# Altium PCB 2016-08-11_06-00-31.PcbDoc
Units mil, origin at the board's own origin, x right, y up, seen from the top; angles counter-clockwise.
Board outline 3200 x 1980 mil, 4 copper layers (Top Layer, MidLayer1, MidLayer2, Bottom Layer); 36 components, 23 nets, 100 pads, 94 vias.
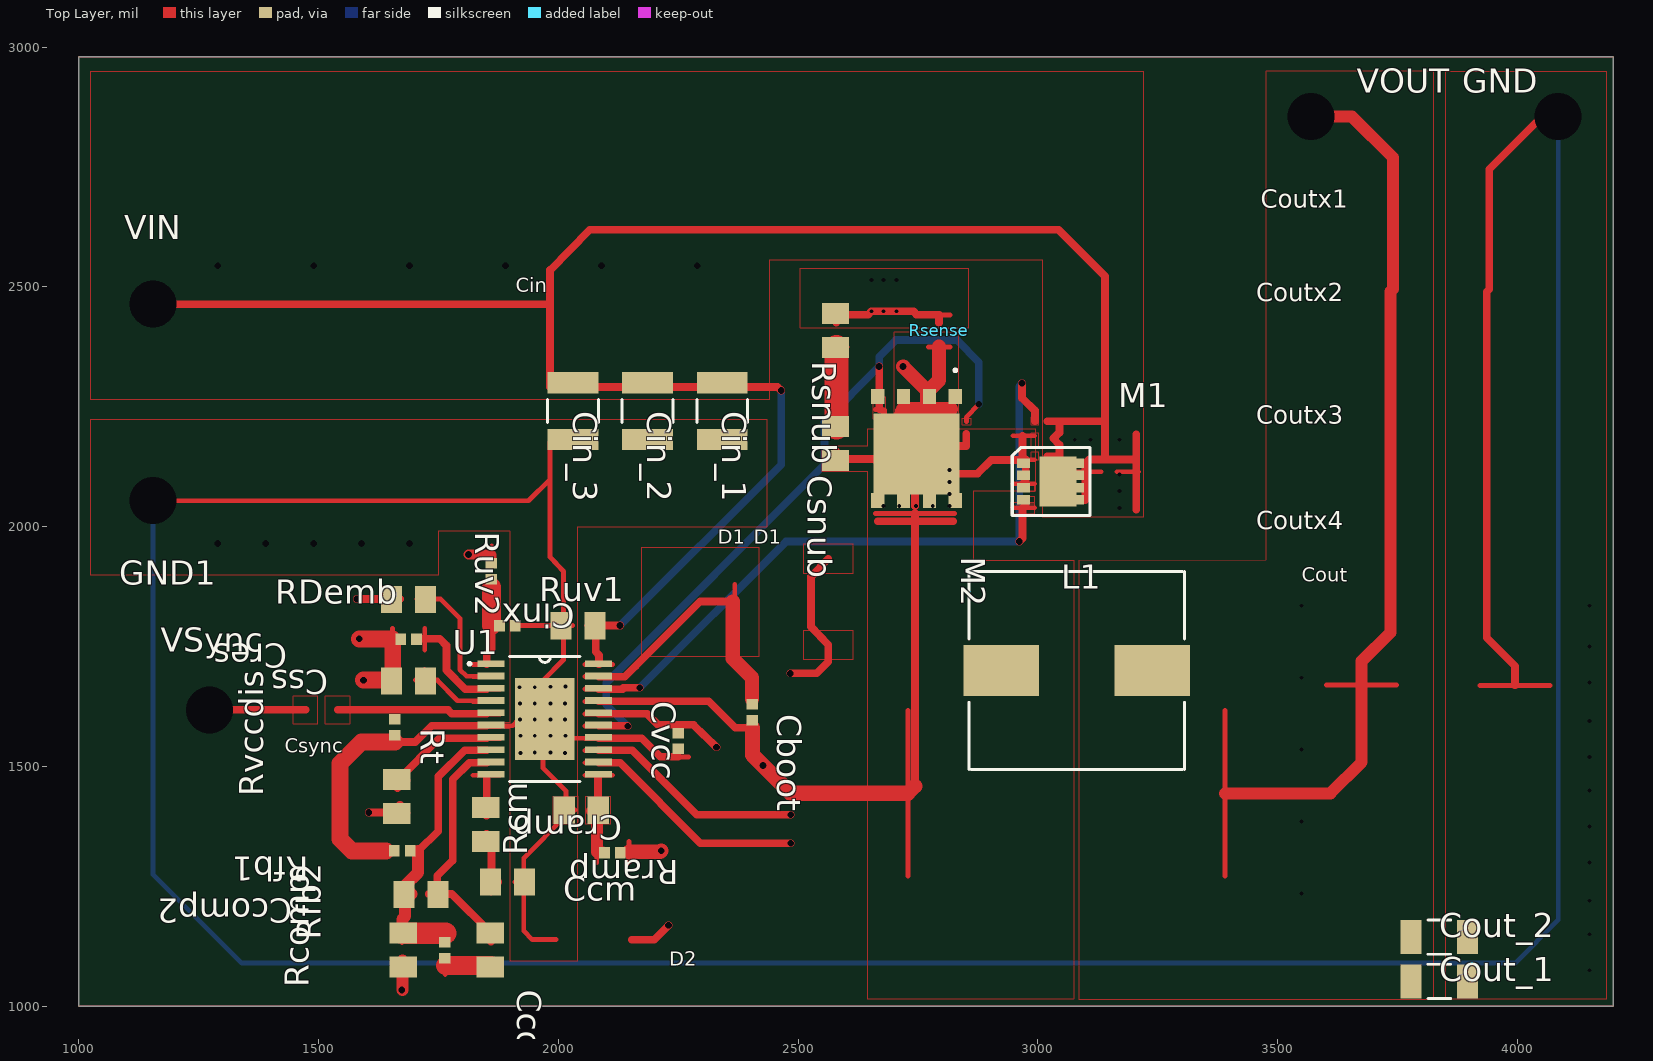
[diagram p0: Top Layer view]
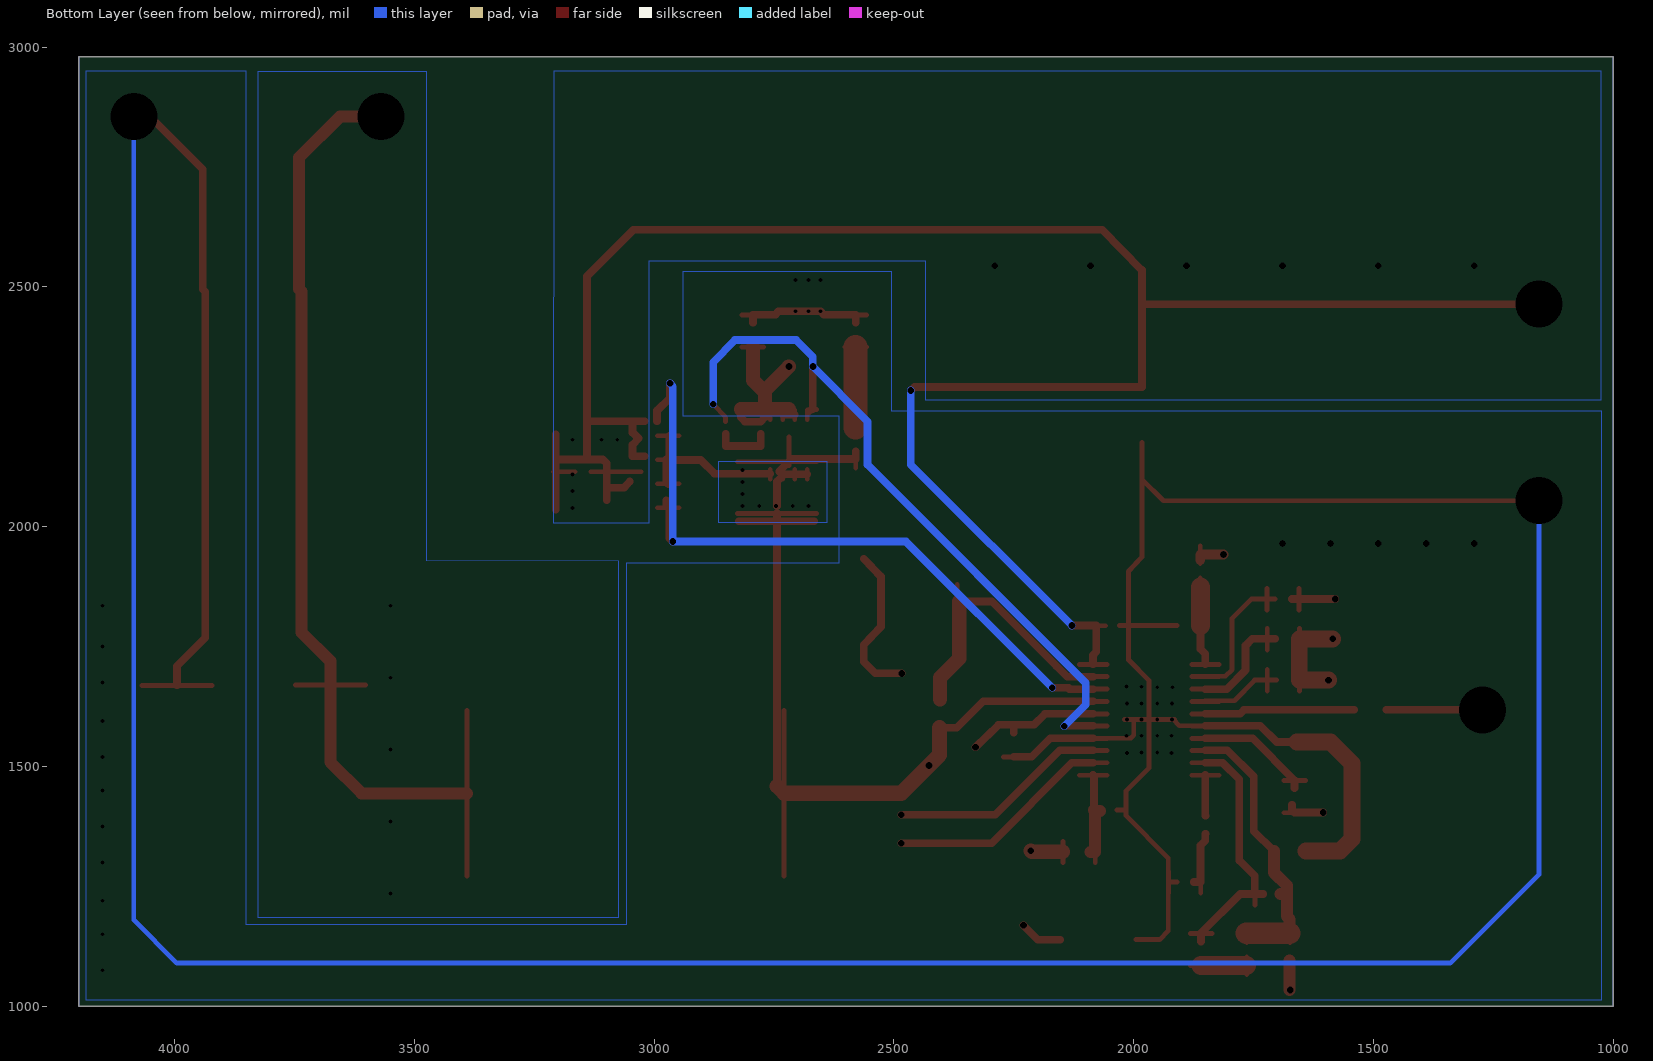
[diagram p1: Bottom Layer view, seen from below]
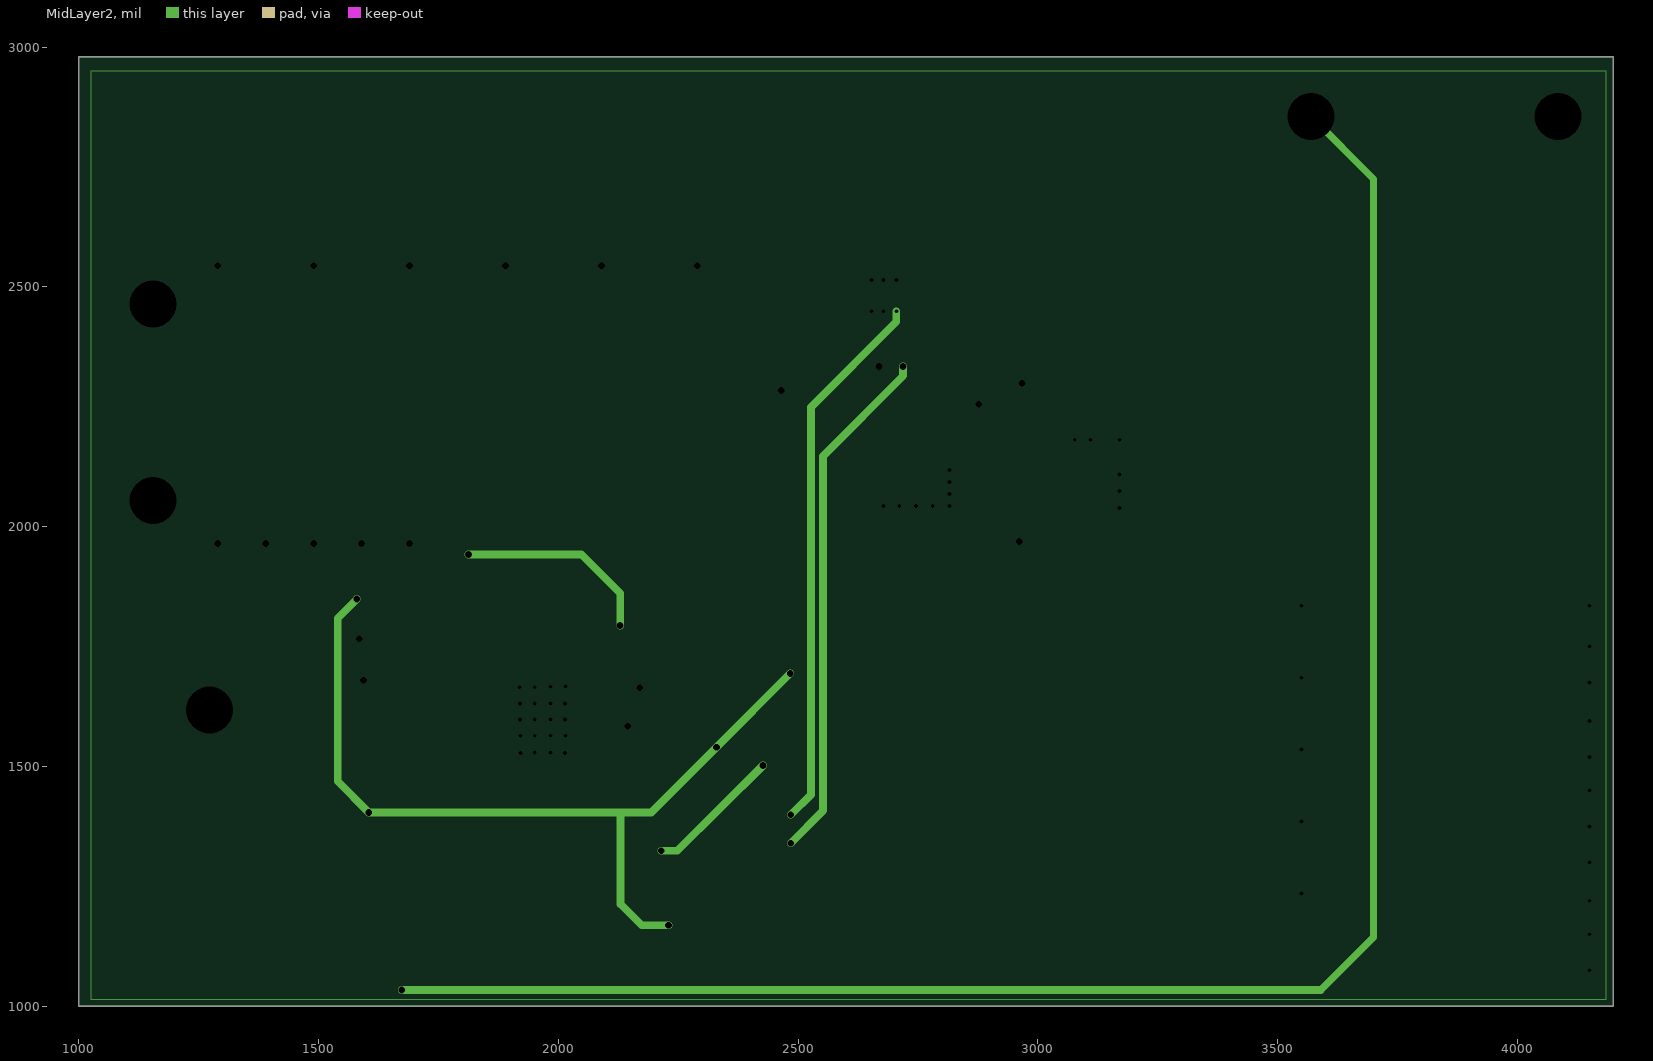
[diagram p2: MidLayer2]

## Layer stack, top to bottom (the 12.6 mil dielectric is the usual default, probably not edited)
Top Layer: signal copper 1.4
Dielectric: core 12.6, FR-4, Dk 4.8
MidLayer1: signal copper 1.4
Dielectric: prepreg 12.6, FR-4, Dk 4.8
MidLayer2: signal copper 1.4
Dielectric: core 12.6, FR-4, Dk 4.8
Bottom Layer: signal copper 1.4

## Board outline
1000,1000 4200,1000 4200,2980 1000,2980

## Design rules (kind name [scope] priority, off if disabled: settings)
PlaneConnect [All] p0: scope1count=1 scope1_0_kind=Board scope1_0_value=Board scope2count=1 scope2_0_kind=Board scope2_0_value=Board commentlength=0 planeconnectstyle=Direct reliefexpansion=20 reliefentries=4 reliefconductorwidth=10 reliefairgap=10
PlaneConnect [All] p1: planeconnectstyle=Direct reliefexpansion=20 reliefentries=4 reliefconductorwidth=10 reliefairgap=10
PolygonConnect [All] p0: scope1count=1 scope1_0_kind=Board scope1_0_value=Board scope2count=1 scope2_0_kind=Board scope2_0_value=Board commentlength=0 connectstyle=Direct reliefconductorwidth=10 reliefentries=4 polygonreliefangle="90 Angle"
PolygonConnect [All] p1: connectstyle=Direct reliefconductorwidth=10 reliefentries=4 polygonreliefangle="90 Angle"

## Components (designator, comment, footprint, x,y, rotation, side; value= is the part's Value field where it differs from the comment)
Cboot "" 0402#1 2405,1613 r270 top
Ccm "" 0805 1894,1259 r0 top
Ccomp1 "" 0805 1858,1117 r270 top
Ccomp2 "" 0805 1714,1233 r180 top
Cin_1 "" 1210_280 2342,2241 r270 top
Cin_2 "" 1210_280 2186,2241 r270 top
Cin_3 "" 1210_280 2031,2241 r270 top
Cinx "" 0805 2041,1793 r180 top
Cout_1 "" 1206_190 3837,1052 r0 top
Cout_2 "" 1206_190 3837,1144 r0 top
Cramp "" 0805 2048,1409 r180 top
Cres "" 0402#1 1688,1765 r180 top
Csnub "" 0805 2578,2173 r270 top
Css "" 0805 1688,1678 r180 top
Cvcc "" 0402#1 2250,1553 r270 top
GND "" TP-1502 4084,2853 r0 top
GND1 "" TP-1502 1155,2052 r0 top
L1 "" MLC1260 3081,1700 r0 top
M1 "" TRANS_NexFET_Q3 3034,2094 r0 top
M2 "" TRANS_NexFET_Q5A 2747,2163 r270 top
Rcm "" 0805 1849,1379 r90 top
Rcomp "" 0402#1 1763,1117 r90 top
RDemb "" 0805 1688,1848 r0 top
Rfb1 "" 0402#1 1675,1324 r180 top
Rfb2 "" 0805 1677,1117 r90 top
Rramp "" 0402#2 2113,1320 r180 top
Rsense "" 0612 2793,2409 r90 top
Rsnub "" 0805 2578,2409 r270 top
Rt "" 0402#1 1659,1582 r270 top
Ruv1 "" 0402#1 1894,1793 r0 top
Ruv2 "" 0402#1 1860,1907 r270 top
Rvccdis "" 0805 1663,1437 r90 top
U1 "" PWP0020A 1972,1599 r0 top
VIN "" TP-1502 1155,2462 r0 top
VOUT "" TP-1502 3568,2853 r0 top
VSync "" TP-1502 1275,1619 r0 top

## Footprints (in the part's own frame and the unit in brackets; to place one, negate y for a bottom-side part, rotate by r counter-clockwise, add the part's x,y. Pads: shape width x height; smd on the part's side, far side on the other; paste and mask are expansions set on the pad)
0402#1 [mil]
  rect 22x24 smd: 1(-16.5,0) 2(16.5,0)
0402#2 [mil]
  rect 22x24 smd: 1(-16.5,0) 1(-16.5,0) 2(16.5,0) 2(16.5,0)
0612 [mil]
0805 [mil]
  rect 44x57 smd: 1(-35.5,0) 2(35.5,0)
1206_190 [mil]
  rect 44x71 smd: 1(-59,0) 2(59,0)
  silkscreen extent -24,-36 24,36
1210_280 [mil]
  rect 44x106 smd: 1(-59,0) 2(59,0)
  silkscreen extent -24,-53 24,53
MLC1260 [mil]
  rect 157.5x106 smd: 1(-157.25,0) 2(157.25,0)
  silkscreen extent -224,-206 224,206
PWP0020A [mil]
  rect 56x14 smd: 1(-112,115.16) 2(-112,89.57) 3(-112,63.98) 4(-112,38.39) 5(-112,12.8) 6(-112,-12.8) 7(-112,-38.39) 8(-112,-63.98) 9(-112,-89.57) 10(-112,-115.16) 11(112,-115.16) 12(112,-89.57) 13(112,-63.98) 14(112,-38.39) 15(112,-12.8) 16(112,12.8) 17(112,38.39) 18(112,63.98) 19(112,89.57) 20(112,115.16)
  rect 124x171 smd: 21(0,0)
  silkscreen extent -160,-130 74,130
TP-1502 [mil]
  round 65 / inner round 0 / far side round 65 hole 32: 1(0,0)
TRANS_NexFET_Q3 [mm]
  rect 0.68x0.5 smd: 1(-1.625,0.975) 2(-1.625,0.325) 3(-1.625,-0.325) 4(-1.625,-0.975)
  rect 0.41x0.5 smd: 5(1.385,-0.975) 6(1.385,-0.325) 7(1.385,0.325) 8(1.385,0.975)
  rect 1.96x2.65 smd: 9(0.205,0)
  silkscreen extent -2.21,-1.8 1.9,1.8
TRANS_NexFET_Q5A [mm]
  rect 0.8x0.7 smd: 1(-2.752,2.055) 2(-2.752,0.685) 3(-2.752,-0.685) 4(-2.752,-2.055) 5(2.752,-2.055) 6(2.752,-0.685) 7(2.752,0.685) 8(2.752,2.055)
  rect 4.3x4.56 smd: 9(0.3,0)
  silkscreen extent -4.22,1.98 -4.07,2.13

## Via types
v1: diameter 0, hole 8, Top Layer to Bottom Layer, 56 vias
v2: diameter 0, hole 14, Top Layer to Bottom Layer, 33 vias
v3: diameter 0, hole 98, Top Layer to Bottom Layer, 5 vias

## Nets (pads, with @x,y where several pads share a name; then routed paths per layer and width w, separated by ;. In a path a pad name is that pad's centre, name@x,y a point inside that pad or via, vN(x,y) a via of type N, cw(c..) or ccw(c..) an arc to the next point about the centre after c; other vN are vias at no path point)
0: Ccm.2 Cin_1.2 Cin_2.2 Cin_3.2 Cinx.2 Cout_1.2 Cout_2.2 Cramp.2 Cres.2 Css.2 Cvcc.2 GND1.1 GND.1 Rfb1.2 Rsnub.1 Rt.2 Ruv1.2 U1.6 U1.13 U1.14 U1.21 | length 12873.8
  Top Layer w10: v3(1155,2054) 1938,2054 1983,2099 ; 1637,1550.5 1682,1550.5 ; Css.2@1654.5,1657 Css.2@1654.5,1702 ; 1654.5,1743 1654.5,1788 ; 1822,1584.5 U1.6@1879,1584.5 ; U1.6@1851,1585 1905,1585 1918,1598 U1.21@1968,1598 ; Ccm.2@1910,1259 Ccm.2@1928,1259 ; Ruv1.2@1910,1794 Cinx.2@2011,1794 ; U1.21@1915,1598 U1.21@2020,1598 ; Ccm.2@1927.5,1236 Ccm.2@1927.5,1281 ; Cin_3.2@1983,2176 1983,2099 ; Cinx.2@1992,1793.5 2029,1793.5 ; 1996,1139 1946,1139 1928,1157 Ccm.2@1928,1259 ; 2030,1794 Cinx.2@2011,1794 ; 2035,1409 Cramp.2@2016,1409 ; U1.13@2056,1533.5 2113,1533.5 ; U1.14@2056,1558.5 2113,1558.5 ; U1.14@2085,1559 2006,1559 2000,1565 2000,1598 U1.21@1968,1598 ; 2227,1519.5 2272,1519.5 ; Rsnub.1@2557,2441.5 Rsnub.1@2602,2441.5 ; 2772,2441.5 2817,2441.5 ; 3922,1669 4068,1669 ; Ccm.2@1928,1259 1928,1309 2016,1397 Cramp.2@2016,1409 ; U1.21@1968,1598 1968,1497 2016,1449 Cramp.2@2016,1409 ; U1.21@1968,1598 1968,1679 2011,1722 Cinx.2@2011,1794 ; 1983,2099 1983,1936 2011,1907 Cinx.2@2011,1794
  Top Layer w16: 1660,1551 1702,1551 1736,1585 U1.6@1851,1585 ; U1.13@2085,1534 2154,1534 2289,1399 v2(2485,1399) ; U1.14@2085,1559 2174,1559 2213,1520 2250,1520 ; Rsnub.1@2580,2425 2580,2442 2646,2442 v1(2653,2449) v1(2678,2449) v1(2705,2449) 2741,2449 2747,2442 2794,2442 2794,2425 ; 3995,1669 3995,1709 3936,1768 3936,2000 3936,2245 3936,2490 3941,2495 3941,2745 4051,2855 v3(4085,2855)
  Top Layer w35: v2(1585,1766) 1655,1766 1655,1680 v2(1594,1680) ; 1641,1324 1570,1324 1545,1349 1545,1506 1590,1551 1660,1551
  MidLayer2 w16: v2(2485,1399) 2527,1441 2527,2249 2705,2427 v1(2705,2449)
  Bottom Layer w10: v3(1155,2054) 1155,1275 1340,1090 3995,1090 4085,1180 v3(4085,2855)
  other v1: 4150,1075 4150,1150 4150,1220 4150,1300 4150,1375 4150,1450 4150,1520 1921,1528 2014,1528 1951,1529 1984,1529 1921,1564 1951,1564 1984,1564 2015,1564 4150,1595 1920,1598 1951,1598 1984,1598 2014,1598 1920,1631 1951,1631 1984,1631 2014,1631 1919,1665 1951,1665 1984,1666 2015,1667 4150,1675 4150,1750 4150,1835 2653,2514 2678,2514 2705,2514
  other v2: 1290,1965 1390,1965 1490,1965 1590,1965 1690,1965
1: Cin_1.1 Cin_2.1 Cin_3.1 Cinx.1 M1.5 M1.6 M1.7 M1.8 M1.9 Ruv2.1 U1.20 VIN.1 | length 5318.6
  Top Layer w10: Ruv2.1@1861.5,1923 1861.5,1960 ; U1.20@2056,1712.5 2113,1712.5 ; Cinx.1@2059,1793.5 Cinx.1@2096,1793.5 ; M1.9@3027,2114.5 3132,2114.5 ; 3165,2114.5 3210,2114.5
  Top Layer w16: v3(1155,2464) 1983,2464 ; U1.20@2085,1713 2085,1732 2078,1739 2078,1794 v2(2129,1794) ; v2(2465,2284) 2457,2291 1983,2291 1983,2464 ; 3020,2147 3045,2147 3045,2171 3032,2184 3045,2196 3045,2220 ; 3020,2220 3045,2220 ; M1.9@3051,2094 3063,2081 3099,2081 ; 3099,2055 3099,2081 ; 3140,2140 3140,2224 ; 3205,2035 3205,2087 3205,2140 ; 3205,2192 3205,2140 ; 1983,2464 1983,2535 2066,2619 3043,2619 3140,2522 3140,2224 ; 3045,2220 3136,2220 3140,2224 ; 3099,2081 3099,2106 3099,2132 3107,2140 3205,2140
  Top Layer w20: v2(1813,1942) 1860,1942 ; Ruv2.1@1861,1930 1861,1941
  MidLayer2 w16: v2(1813,1942) 2048,1942 2129,1861 v2(2129,1794)
  Bottom Layer w16: v2(2129,1794) 2465,2129 v2(2465,2284)
  other v1: 3170,2039 3170,2074 3170,2109 3077,2181 3110,2181 3170,2181
  other v2: 1290,2544 1490,2544 1690,2544 1890,2544 2090,2544 2290,2544
2: Css.1 U1.4 | length 270.1
  Top Layer w10: Css.1@1702,1680 1722,1680 1748,1680 1790,1637 U1.4@1852,1637 ; Css.1@1721.5,1657 Css.1@1721.5,1702 ; 1822,1635.5 U1.4@1879,1635.5
3: M2.4 U1.15 | length 1658.9
  Top Layer w10: U1.15@2056,1584.5 2113,1584.5 ; 2661,2244.5 2676,2244.5 ; 2669,2245 2669,2244 2681,2233 ; 2681,2223 2681,2243 ; 2851,2219 2851,2228 v2(2877,2255)
  Top Layer w16: U1.15@2085,1585 2143,1585 v2(2145,1584) ; 2669,2245 v2(2669,2334)
  Bottom Layer w16: v2(2145,1584) 2100,1629 2100,1674 2555,2129 2555,2219 v2(2669,2334) 2669,2354 2704,2389 2832,2389 2877,2343 v2(2877,2255)
4: Ruv1.1 Ruv2.2 U1.1 | length 259.1
  Top Layer w10: 1822,1712.5 U1.1@1879,1712.5 ; 1861.5,1856 Ruv2.2@1861.5,1893
  Top Layer w16: U1.1@1851,1713 1851,1735 1861,1745 1861,1794
  Top Layer w40: 1861,1794 1861,1874
5: Rt.1 U1.5 | length 416.3
  Top Layer w10: 1637,1617.5 1682,1617.5 ; 1822,1609.5 U1.5@1879,1609.5
  Top Layer w16: 1540,1618 1659,1618 1660,1618 1770,1618 1778,1610 U1.5@1851,1610
6: Cres.1 U1.3 | length 322.7
  Top Layer w10: 1721.5,1743 1721.5,1788 ; 1822,1661.5 U1.3@1879,1661.5 ; U1.3@1851,1662 U1.3@1852,1662
  Top Layer w16: Cres.1@1705,1766 1722,1766 1753,1766 1767,1752 1767,1701 1806,1661 U1.3@1851,1661
8: Ccomp1.1 Ccomp2.1 U1.9 | length 665.7
  Top Layer w10: Ccomp2.1@1747.5,1211 Ccomp2.1@1747.5,1256 ; 1822,1507.5 U1.9@1879,1507.5 ; Ccomp1.1@1837,1151.5 Ccomp1.1@1882,1151.5
  Top Layer w16: Ccomp2.1@1730,1234 Ccomp2.1@1748,1234 ; U1.9@1851,1508 1815,1508 1780,1473 1780,1304 1748,1272 Ccomp2.1@1748,1234 ; Ccomp1.1@1860,1135 1860,1152 1778,1234 Ccomp2.1@1748,1234
9: Ccomp2.2 Rcomp.2 Rfb1.1 Rfb2.2 U1.8 | length 760.9
  Top Layer w10: Rfb2.2@1674.5,1133 Rfb2.2@1674.5,1170 ; Ccomp2.2@1680.5,1211 Ccomp2.2@1680.5,1256 ; Rcomp.2@1764.5,1133 1764.5,1170 ; 1822,1533.5 U1.8@1879,1533.5
  Top Layer w16: 1708,1324 1750,1365 1750,1479 1805,1534 U1.8@1851,1534
  Top Layer w25: Rfb2.2@1675,1152 1675,1181 1681,1188 Ccomp2.2@1681,1234 ; Ccomp2.2@1694,1234 Ccomp2.2@1681,1234 ; 1708,1324 1708,1279 1681,1252 Ccomp2.2@1681,1234
  Top Layer w45: Rfb2.2@1675,1152 1765,1152
10: Cramp.1 Rramp.2 U1.11 | length 283.7
  Top Layer w10: U1.11@2056,1481.5 2113,1481.5 ; 2080.5,1299 2080.5,1344
  Top Layer w16: Cramp.1@2083,1409 2083,1480 U1.11@2085,1482
  Top Layer w25: Cramp.1@2070,1407 Cramp.1@2081,1407 ; Cramp.1@2083,1409 Cramp.1@2081,1407 ; Rramp.2@2090,1322 2081,1322 Cramp.1@2081,1407
11: Cout_1.1 Cout_2.1 L1.2 Rfb2.1 VOUT.1 | length 6231.8
  Top Layer w10: Rfb2.1@1674.5,1066 Rfb2.1@1674.5,1103 ; 3390,1271 3390,1617 ; 3602,1670 3748,1670
  Top Layer w25: 1675,1034 1675,1085 1675,1094 Rfb2.1@1675,1095 ; 3390,1444 3610,1444 3675,1509 3675,1670 3675,1720 3735,1779 3735,2000 3735,2245 3735,2490 3740,2495 3740,2745 3740,2770 3655,2855 v3(3570,2855)
  MidLayer2 w15: v3(3570,2855) 3700,2725 3700,1144 3590,1034
  MidLayer2 w16: v2(1674,1034) 3590,1034
  other v1: 3550,1235 3550,1385 3550,1535 3550,1685 3550,1835
12: M2.1 M2.2 M2.3 U1.12 | length 2164
  Top Layer w10: U1.12@2056,1507.5 2113,1507.5 ; 2707,2223 2707,2243 ; 2711,2244.5 2726,2244.5 ; 2732,2223 2732,2243 ; 2758,2223 2758,2243 ; 2761,2244.5 2776,2244.5 ; 2772,2374.5 2817,2374.5 ; 2811,2244.5 2826,2244.5
  Top Layer w16: U1.12@2085,1508 2129,1508 2296,1340 v2(2485,1340) ; 2719,2248 2719,2246 2707,2233 2732,2233 ; 2769,2228 2769,2245 ; 2819,2228 2819,2248
  Top Layer w30: 2719,2245 2769,2245 ; v2(2719,2334) 2769,2284 M2.2@2769,2280 ; 2794,2375 2794,2305 M2.2@2769,2280 ; 2819,2245 2769,2245 ; 2769,2245 M2.2@2769,2280
  MidLayer2 w16: v2(2485,1340) 2552,1408 2552,2147 2719,2315 v2(2719,2334)
13: Cboot.2 Csnub.2 L1.1 M1.1 M1.2 M1.3 M2.5 M2.6 M2.7 M2.8 M2.9 Rramp.1 U1.17 | length 3763.5
  Top Layer w10: U1.17@2056,1635.5 2113,1635.5 ; 2147.5,1299 2147.5,1344 ; Csnub.2@2579.5,2122 Csnub.2@2579.5,2159 ; 2661,2027.5 2826,2027.5 ; M2.9@2661,2135.5 M2.9@2826,2135.5 ; M2.9@2681,2099 M2.9@2681,2119 ; M2.9@2707,2099 M2.9@2707,2119 ; M2.9@2719,2127 M2.9@2719,2187 ; 2729,1271 2729,1617 ; M2.9@2732,2099 M2.9@2732,2119 ; M2.9@2758,2099 M2.9@2758,2119 ; 2948,2089.5 2993,2089.5 ; 2948,2139.5 2993,2139.5 ; 2948,2189.5 2993,2189.5
  Top Layer w16: U1.17@2085,1636 2314,1636 2369,1581 2405,1581 ; Csnub.2@2580,2157 2580,2141 2714,2141 M2.9@2739,2115 ; 2666,2011 2718,2011 2744,2011 ; M2.9@2681,2109 2707,2109 2729,2109 2744,2094 2744,2043 ; 2744,1459 2744,2011 ; 2744,2028 2744,2011 ; M2.9@2758,2110 2874,2110 2903,2139 2968,2139 2968,2189 ; M2.9@2769,2228 2778,2219 2811,2219 M2.9@2819,2228 ; M2.9@2778,2194 2778,2168 2851,2168 2851,2194 ; 2823,2011 2771,2011 2744,2011 ; M1.3@2968,2089 2970,2089 2971,2090 2975,2094 2975,2106 2975,2132 M1.1@2975,2140
  Top Layer w30: 2148,1322 2213,1322 v2(2215,1324) ; 2729,1444 2744,1459
  Top Layer w32: 2405,1581 2405,1524 2485,1444 2729,1444
  MidLayer2 w16: v2(2215,1324) 2248,1324 v2(2427,1502)
  other v1: 2678,2043 2711,2043 2746,2043 2781,2043 2816,2043 2816,2068 2816,2093 2816,2118
14: M1.4 U1.18 | length 1620.8
  Top Layer w10: U1.18@2056,1661.5 2113,1661.5 ; 2948,2039.5 2993,2039.5
  Top Layer w16: U1.18@2085,1661 2134,1661 2136,1664 v2(2170,1664) ; v2(2961,1969) 2968,1976 2968,2039 2975,2045 M1.4@2975,2055 ; v2(2967,2299) 2967,2268 2994,2242 2994,2220
  Bottom Layer w16: v2(2170,1664) 2475,1969 v2(2961,1969) 2961,2292 v2(2967,2299)
15: Cvcc.1 RDemb.1 Rvccdis.1 U1.16 | length 2934
  Top Layer w10: Rvccdis.1@1642,1403.5 Rvccdis.1@1687,1403.5 ; RDemb.1@1655.5,1826 RDemb.1@1655.5,1871 ; U1.16@2056,1609.5 2113,1609.5 ; 2227,1586.5 2272,1586.5 ; 2526,1816 2526,1880
  Top Layer w16: v2(1580,1849) 1656,1849 RDemb.1@1670,1849 ; v2(1605,1404) 1665,1404 1670,1410 Rvccdis.1@1670,1420 ; U1.16@2085,1610 2185,1610 2208,1587 2250,1587 ; 2153,1139 2200,1139 v2(2230,1169) ; Cvcc.1@2250,1570 2250,1587 ; v2(2330,1540) 2282,1587 2250,1587 ; v2(2484,1694) 2539,1694 2563,1718 2563,1754 2527,1791 2527,1849 2527,1896 2563,1933
  MidLayer2 w16: v2(1580,1849) 1540,1809 1540,1469 v2(1605,1404) 2130,1404 ; v2(2230,1169) 2174,1169 2130,1213 2130,1404 ; v2(2484,1694) v2(2330,1540) 2194,1404 2130,1404
16: Cboot.1 U1.19 | length 685.6
  Top Layer w10: U1.19@2056,1687.5 2113,1687.5 ; 2368,1816 2368,1880
  Top Layer w16: U1.19@2085,1687 2139,1687 2161,1709 2296,1844 2364,1844
  Top Layer w30: 2364,1844 2364,1725 2404,1685 Cboot.1@2404,1640
17: Ccomp1.2 Rcomp.1 | length 177
  Top Layer w10: 1764.5,1066 Rcomp.1@1764.5,1103 ; Ccomp1.2@1837,1084.5 Ccomp1.2@1882,1084.5
  Top Layer w40: 1765,1085 Ccomp1.2@1860,1085
18: VSync.1 | length 200
  Top Layer w16: v3(1273,1618) 1472,1618 1473,1618
19: Csnub.1 Rsnub.2 | length 250
  Top Layer w10: Rsnub.2@2557,2374.5 Rsnub.2@2602,2374.5 ; Csnub.1@2579.5,2189 Csnub.1@2579.5,2226
  Top Layer w50: Csnub.1@2580,2207 Rsnub.2@2580,2375
21: Rvccdis.2 U1.7 | length 340.7
  Top Layer w10: Rvccdis.2@1642,1470.5 Rvccdis.2@1687,1470.5 ; 1822,1558.5 U1.7@1879,1558.5
  Top Layer w16: Rvccdis.2@1665,1455 1665,1471 1752,1559 U1.7@1851,1559
28: Rcm.2 U1.10 | length 143
  Top Layer w10: 1822,1481.5 U1.10@1879,1481.5
  Top Layer w16: Rcm.2@1850,1397 1851,1397 1851,1412 U1.10@1851,1482
29: RDemb.2 U1.2 | length 378.4
  Top Layer w10: RDemb.2@1705,1849 1723,1849 1755,1849 1795,1809 1795,1702 1809,1688 U1.2@1852,1688 ; RDemb.2@1722.5,1826 RDemb.2@1722.5,1871 ; 1822,1687.5 U1.2@1879,1687.5
36: Ccm.1 Rcm.1 | length 164.6
  Top Layer w10: Ccm.1@1860.5,1236 Ccm.1@1860.5,1281
  Top Layer w16: Rcm.1@1850,1360 1851,1359 1851,1345 1861,1335 1861,1259 Ccm.1@1875,1259

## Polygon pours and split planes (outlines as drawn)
18 on Top Layer " " (solid, pour order 0): 1447,1588 1447,1647 1498,1647 1498,1588
5 on Top Layer " " (solid, pour order 1): 1514,1588 1514,1647 1565,1647 1565,1588
3 on Top Layer " " (solid, pour order 2): 2657,2224 2657,2271 2682,2271 2682,2224
14 on Top Layer " " (solid, pour order 3): 2958,2047 2958,2063 2992,2063 2992,2047
13 on Top Layer " " (solid, pour order 4): 2958,2073 2958,2089 2992,2089 2992,2073
3 on Top Layer " " (solid, pour order 5): 2842,2211 2842,2226 2860,2226 2860,2211
13 on Top Layer " " (solid, pour order 6): 2769,2211 2769,2226 2787,2226 2787,2211
13 on Top Layer " " (solid, pour order 7): 2794,2211 2794,2226 2827,2226 2827,2211
14 on Top Layer " " (solid, pour order 8): 2986,2211 2986,2229 3001,2229 3001,2211
13 on Top Layer " " (solid, pour order 9): 2986,2138 2986,2156 3001,2156 3001,2138
13 on Top Layer " " (solid, pour order 10): 2986,2163 2986,2196 3001,2196 3001,2163
14 on Top Layer " " (solid, pour order 11): 2945,2026 2945,2051 2992,2051 2992,2026
10 on Top Layer " " (solid, pour order 12): 2057,1379 2057,1438 2108,1438 2108,1379
16 on Top Layer " " (solid, pour order 13): 2174,1729 2174,1957 2418,1957 2418,1729
15 on Top Layer " " (solid, pour order 14): 2512,1902 2512,1964 2614,1964 2614,1902
15 on Top Layer " " (solid, pour order 15): 2512,1722 2512,1784 2614,1784 2614,1722
12 on Top Layer " " (solid, pour order 19): 2700,2215 2835,2215 2835,2405 2700,2405
11 on Top Layer " " (solid, pour order 20): 3085,1015 3825,1015 3825,2950 3475,2950 3475,1930 3085,1929
13 on Top Layer " " (solid, pour order 21): 2995,2204 2995,2074 2865,2074 2865,1930 3075,1930 3075,1015 2645,1015 2645,2114 2550,2114 2550,2169 2645,2169 2645,2204
1 on Top Layer " " (solid, pour order 22): 1025,2950 3220,2950 3220,2020 3010,2020 3010,2555 2440,2555 2440,2265 1025,2265
0 on Top Layer " " (solid, pour order 23): 1990,1379 1990,1438 2041,1438 2041,1379
0 on Top Layer " " (solid, pour order 27): 3850,2950 4185,2950 4185,1015 3850,1015
0 on Top Layer " " (solid, pour order 28): 2505,2539 2855,2539 2855,2414 2505,2414
0 on Top Layer " " (solid, pour order 29): 2040,1094 1900,1094 1900,1579 1815,1579 1815,1592 1900,1592 1900,1990 1750,1990 1750,1899 1025,1899 1025,2224 2435,2224 2435,1999 2040,1999
11 on Bottom Layer " " (solid, pour order 16): 3075,1185 3825,1185 3825,2950 3475,2950 3475,1930 3075,1929
1 on Bottom Layer " " (solid, pour order 17): 1025,2950 3209,2950 3210,2008 3010,2008 3010,2554 2435,2554 2435,2265 1025,2265
13 on Bottom Layer " " (solid, pour order 18): 2640,2136 2640,2008 2865,2008 2865,2136
0 on Bottom Layer " " (solid, pour order 26): 1024,2241 2505,2241 2505,2531 2940,2531 2940,2231 2615,2231 2615,1924 3058,1924 3058,1170 3850,1170 3850,2950 4185,2950 4185,1014 1024,1014
0 on MidLayer1 " " (solid, pour order 24): 1025,2950 4185,2950 4185,1015 1025,1015
0 on MidLayer2 " " (solid, pour order 25): 1025,2950 1025,1015 4185,1015 4185,2950
no net on Top Solder "Top Layer-No Net" (solid, remove dead copper): 2733.81,2287.11 2706.25,2287.11 2706.25,2255.62 2733.81,2255.62
no net on Top Solder "Top Layer-No Net" (solid, remove dead copper): 2679.87,2287.11 2652.31,2287.11 2652.31,2255.62 2679.87,2255.62
no net on Top Solder "Top Layer-No Net" (solid, remove dead copper): 2679.87,2070.38 2652.32,2070.38 2652.32,2038.89 2679.87,2038.89
no net on Top Solder "Top Layer-No Net" (solid, remove dead copper): 2733.81,2070.38 2706.25,2070.38 2706.25,2038.89 2733.81,2038.89
no net on Top Solder "Top Layer-No Net" (solid, remove dead copper): 2787.75,2070.38 2760.19,2070.38 2760.19,2038.89 2787.75,2038.89
no net on Top Solder "Top Layer-No Net" (solid, remove dead copper): 2841.69,2070.38 2814.13,2070.38 2814.13,2038.89 2841.69,2038.89
no net on Top Solder "Top Layer-No Net" (solid, remove dead copper): 2836.76,2070.48 2836.76,2239.77 2657.24,2239.77 2657.24,2070.48

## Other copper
Multi-Layer:
  the board outline again, w1

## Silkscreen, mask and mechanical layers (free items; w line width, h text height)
Top Overlay:
  text "Coutx1" at 3465,2665 h37
  text "Cin" at 1911,2489 h30
  text "Coutx2" at 3455,2470 h37
  text "Coutx3" at 3455,2215 h37
  text "Coutx4" at 3455,1995 h37
  text "D1" at 2333,1964 h30
  text "D1" at 2408,1964 h30
  text "Cout" at 3550,1885 h30
  text "Csync" at 1430,1529 h30
  text "D2" at 2231,1084 h30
